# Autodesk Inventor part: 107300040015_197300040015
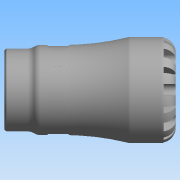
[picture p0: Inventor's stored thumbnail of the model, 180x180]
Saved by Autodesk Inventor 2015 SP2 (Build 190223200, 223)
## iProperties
Created: 2016-12
Part Number: 107300040015_197300040015
Material: Generic
Description: PLASSON FEMALE INTEGRAL BRASS THREAD 40X1.1/2" SERIES 1
Document SubType Name: Modeling
Designer: KIM
Density: 1 g/cm^3
Appearance: Default
Author: KIM
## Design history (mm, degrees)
derived "1073.ipt"
feature "Solid1::1073.ipt"
tag "TaggingFeature1"
body "Solid1"
other parameters: "d0" = 113, "d1" = 30.66, "d6" = 73, "d8" = 59.5, "d13" = 8, "d14" = 8, "d15" = 0, "d17" = 360 deg, "d19" = 8 deg, "d20" = 0.8, "d21" = 0.8, "d22" = 8 deg, "d24" = 0, "d26" = 360 deg, "d32" = 7, "d33" = 7, "d39" = 1.34535, "d42" = 44.845, "d43" = 54.6, "d46" = 3.33333, "d47" = 21, "d48" = 42.60275, "d50" = 6.27, "d51" = 0.7, "d54" = 14, "d55" = 8.8, "d57" = 15.68, "d58" = 0, "d68" = 360 deg, "d72" = 0.8, "d74" = 0, "d76" = 11.9, "H_" = 113, "l_" = 73, "G_" = 44.845, "l_2" = 21, "d9" = 10, "d49" = 19
